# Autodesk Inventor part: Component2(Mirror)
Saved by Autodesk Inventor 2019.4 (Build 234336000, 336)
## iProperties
Created: 2020-06
Part Number: Component2(Mirror)
Material: Generic
Document SubType Name: Modeling
Designer: Administrator
Density: 1 g/cm^3
Appearance: Default
Title: Component2(Mirror)
Author: Administrator
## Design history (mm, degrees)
